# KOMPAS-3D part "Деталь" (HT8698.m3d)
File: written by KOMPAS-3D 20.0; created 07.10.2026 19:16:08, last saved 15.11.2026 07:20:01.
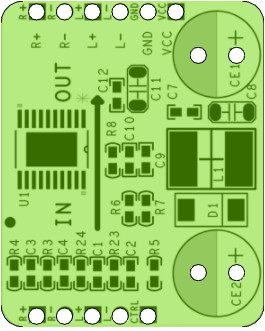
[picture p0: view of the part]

Document properties: Полное имя файла: D:\myProjects\Progect_esp32\box_compas\усилитель\HT8698.m3d

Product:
- Part/product: Деталь
    Масса: 0.00813166

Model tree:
1. Эскиз:1
2. Элемент выдавливания:1
     Расстояние 1 = 1.5
3. Эскиз:2  (with: Элемент выдавливания:1)
4. Элемент выдавливания:2
     Расстояние 1 = 12
5. Эскиз:3  (with: Элемент выдавливания:1)
6. Элемент выдавливания:3
     Расстояние 2 = 1.5
7. Массив по сетке:1  (with: Элемент выдавливания:3, Эскиз:3)  (5 pattern instances)
     Шаг 1 = 10; Угол раствора = -90; Шаг 2 = 2.54
8. Эскиз:4  (with: Элемент выдавливания:1, Элемент выдавливания:3)
9. Элемент выдавливания:4
     Расстояние 2 = 1.5
10. Массив по сетке:2  (with: Элемент выдавливания:4, Эскиз:4)  (6 pattern instances)
     Шаг 1 = 10; Угол раствора = -90; Шаг 2 = 2.54
11. Скругление:1  (with: Элемент выдавливания:1)
     Радиус = 2
12. Эскиз:5  (with: Элемент выдавливания:1, Элемент выдавливания:3, Элемент выдавливания:4)
13. Эскиз:6  (with: Элемент выдавливания:1)
14. Элемент выдавливания:5
15. Массив по сетке:3  (with: Элемент выдавливания:5, Эскиз:6)  (4 pattern instances)
     Шаг 1 = 3.5; Угол раствора = -90; Шаг 2 = 20

Referenced files in D:\RicWork\Project-EPS32\box_compas\: chHT8698.png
